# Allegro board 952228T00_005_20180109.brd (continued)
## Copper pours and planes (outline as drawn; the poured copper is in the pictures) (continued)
(no net) on BOTTOM: 84.28,6 83.04,6 83.04,5.19 82.96,5.12 81.31,5.12 81.16,5.27 81.16,6.64 80.53,7.27 77.05,7.27 76.72,6.94 76.72,5.32 76.89,5.14 79.08,5.14 80.02,4.2 83.32,4.2 83.65,4.53 84.26,4.53 84.31,4.58 84.31,5.98
FAN1_PWR on TOP: 24.77,9.31 24.77,7.12 24.39,6.74 22,6.74 21.93,6.82 21.93,10.27 28.23,16.57 37.84,16.57 38.05,16.36 38.05,14.49 29.95,14.49
FAN1_PWR on BOTTOM: 38.11,21.16 38.11,16.81 37.88,16.59 37.41,16.59 37.21,16.38 37.21,14.71 37.4,14.51 39.07,14.51 39.81,15.25 39.81,21.16
FAN1_PWR on BOTTOM: 24.42,6.72 22,6.72 21.83,6.89 21.83,9.2 22.13,9.51 24.52,9.51 24.67,9.36 24.67,6.97
FAN2_PWR on TOP: 79.59,7.48 82.33,7.48 82.34,7.49 88.04,7.49 90.53,9.98 90.53,17.13 90.56,17.16 90.56,18.15 90.28,18.43 90.28,18.68 90.06,18.9 88.6,18.9 88.59,18.89 88.59,11.01 87.05,9.47 79.64,9.47 79.59,9.43
FAN2_PWR on BOTTOM: 89.44,18.09 89.39,18.04 89.39,17.28 89.52,17.16 91.04,17.16 91.04,18.08 91.12,18.16 91.12,20.3 91.12,20.31 91.12,20.84 91.08,20.88 89.64,20.88 89.44,20.68
FAN2_PWR on BOTTOM: 82.3,7.58 79.71,7.58 79.43,7.86 79.43,8.6 79.79,8.95 82.3,8.95 82.35,8.9 82.35,7.63
FAN3_PWR on TOP: 131.66,7.99 102.22,7.99 102.22,9.59 130.97,9.59 131.2,9.81 131.2,13.17 134.32,16.29 143.01,16.29 143.7,15.61 143.7,14.67 135.77,14.67 133.18,12.08 133.18,9.51
FAN3_PWR on BOTTOM: 142.61,14.51 143.61,14.51 144.64,15.54 144.64,20.9 143.28,20.9 143.28,16.41 142.29,15.42 142.29,14.83
FAN3_PWR on BOTTOM: 102.24,8.77 103.64,8.77 103.74,8.67 103.74,6.64 103.61,6.51 102.37,6.51 102.22,6.66 102.22,8.75
FAN4_PWR on TOP: 194.98,20.1 185.94,11.07 185.94,10.87 187.28,9.53 187.78,9.53 197.11,18.86 197.11,19.75 196.76,20.1
FAN5_PWR on TOP: 247.76,15.66 247.94,15.83 247.94,18.72 248.17,18.95 249.47,18.95 249.82,18.61 249.82,15.15 248.57,13.9 218.7,13.9 217.99,14.62 204.12,14.62 202.57,13.07 200.97,13.07 200.9,13.14 200.9,14.49 202.62,16.22 227.32,16.22 227.88,15.66
FAN5_PWR on BOTTOM: 202.45,11.74 201.05,11.74 200.9,11.9 200.9,14.51 202.57,14.51 202.78,14.31 202.78,12.08
FAN_GND on TOP (solid shape): outline of 241 points within 9.48,20.07 16.48,27.08
FAN_GND on TOP (solid shape): outline of 241 points within 49.48,5.07 56.48,12.08
FAN_GND on TOP (solid shape): outline of 241 points within 149.48,5.07 156.48,12.08
FAN_GND on TOP (solid shape): outline of 241 points within 209.48,20.07 216.48,27.08
FAN_GND on TOP (solid shape): outline of 264 points within 112.85,18.45 121.11,26.7
FAN_GND on TOP (solid shape): outline of 264 points within 250.91,4.45 259.17,12.7
FAN_GND on BOTTOM (solid shape): outline of 241 points within 9.48,20.07 16.48,27.08
FAN_GND on BOTTOM (solid shape): outline of 241 points within 49.48,5.07 56.48,12.08
FAN_GND on BOTTOM (solid shape): outline of 241 points within 149.48,5.07 156.48,12.08
FAN_GND on BOTTOM (solid shape): outline of 241 points within 209.48,20.07 216.48,27.08
FAN_GND on BOTTOM (solid shape): outline of 264 points within 112.85,18.45 121.11,26.7
FAN_GND on BOTTOM (solid shape): outline of 264 points within 250.91,4.45 259.17,12.7
FAN_GND on TOP: outline of 155 points within 0.51,0.51 272.49,30.29 ; 10 cut-outs
FAN_GND on BOTTOM: outline of 145 points within 0.51,0.51 272.49,30.29 ; 25 cut-outs
FAN_GND on G02: outline of 86 points within 0.51,0.51 272.49,30.29
FAN_GND on T03: outline of 86 points within 0.51,0.51 272.49,30.29 ; 22 cut-outs
FAN_GND on P04: outline of 84 points within 0.51,0.51 272.49,30.29
FAN_GND on G05: outline of 84 points within 0.51,0.51 272.49,30.29
FAN_P3V3 on G05: 1.52,1.52 1.52,22.18 8.98,22.18 11.3,19.6 14.76,19.65 14.76,19.36 17.79,16.34 20.81,19.36 20.81,20.02 39.49,20.02 39.49,19.36 42.51,16.34 45.53,19.36 45.53,20.02 67.27,20.02 67.27,19.36 70.29,16.34 73.31,19.36 73.31,20.02 91.99,20.02 91.99,19.36 95.01,16.34 98.03,19.36 98.03,20.02 112.53,20.02 115.87,17.57 119.93,18.38 123.29,16.38 125.81,19.36 125.81,20.02 144.49,20.02 144.49,19.36 147.51,16.34 150.53,19.36 150.53,21.87 172.27,21.87 172.27,19.36 175.29,16.34 178.31,19.36 178.31,19.61 196.98,19.61 196.98,19.36 200.01,16.33 203.04,19.36 203.04,19.63 224.76,19.63 224.76,19.36 227.79,16.33 230.82,19.36 230.82,19.63 249.49,19.63 249.49,19.36 252.51,16.34 255.53,19.36 255.53,27.8 255.97,28.84 257.01,29.28 271.47,29.28 271.47,1.52 ; 3 cut-outs
FAN_P12V on BOTTOM (solid shape): 81.16,6.64 81.16,5.27 81.31,5.12 82.96,5.12 83.04,5.19 83.04,6 83.7,6 83.7,5.95 84.31,5.95 84.31,4.58 84.26,4.53 83.65,4.53 83.32,4.2 80.02,4.2 79.08,5.14 76.89,5.14 76.72,5.32 76.72,6.94 77.05,7.27 80.53,7.27
FAN_P12V on BOTTOM: 107.53,6.44 106.23,6.44 106.05,6.61 104.88,6.61 104.53,6.26 102.32,6.26 101.73,6.84 99.04,6.84 98.76,6.56 98.76,5.17 98.97,4.96 107.32,4.96 107.53,5.17
FAN_P12V on BOTTOM: 28.3,7.1 25.05,7.1 24.75,6.79 24.75,2.96 24.93,2.78 26.63,2.78 26.91,3.06 26.91,4.86 27.67,5.62 28.28,5.62 28.33,5.67 28.33,7.07
FAN_P12V on BOTTOM: 203.28,11.87 205.9,11.87 207.14,10.63 208.24,10.63 208.57,10.3 208.57,8.7 208.44,8.57 205.37,8.57 205.29,8.65 205.29,10.4 205.19,10.5 203.28,10.5 203.26,10.53 203.26,11.85
FAN_P12V on BOTTOM: 189.29,7.45 188.45,7.45 187.84,6.84 185.91,6.84 185.73,7.02 185.73,8.42 184.49,9.66 179.64,9.66 179.64,8.14 181.6,8.14 182.28,7.47 183.18,7.47 183.7,6.94 183.7,6.66 184.92,5.45 188.96,5.45 189.39,5.88 189.39,7.35
FAN_P12V on BOTTOM: 262.69,26.38 261.6,25.28 261.6,18.45 265.79,14.26 265.79,7.22 265.74,7.17 260.43,7.17 260.43,12.1 257.44,15.1 257.44,26.86 259.52,28.94 269.76,28.94 270.19,28.51 270.19,26.96 269.6,26.38
FAN_P12V on P04: 1.52,1.52 1.52,29.28 13.29,29.28 14.33,28.84 14.76,27.8 14.76,27.19 8.81,23.43 14.76,19.67 14.76,19.36 17.79,16.34 20.81,19.36 20.81,20.02 39.49,20.02 39.49,19.36 42.51,16.34 45.53,19.36 45.53,20.02 67.27,20.02 67.27,19.36 70.29,16.34 73.31,19.36 73.31,20.02 91.99,20.02 91.99,19.36 95.01,16.34 98.03,19.36 98.03,20.02 112.54,20.02 115.88,17.57 119.93,18.38 123.28,16.38 125.81,19.36 125.81,20.02 144.45,20.02 144.49,19.98 144.49,19.36 147.51,16.34 150.53,19.36 150.53,21.88 172.27,21.88 172.27,19.36 175.29,16.34 178.31,19.36 178.31,19.61 196.98,19.61 196.98,19.36 200.01,16.33 203.04,19.36 203.04,19.63 224.76,19.63 224.76,19.36 227.79,16.33 230.82,19.36 230.82,19.66 249.49,19.66 249.49,19.36 252.51,16.34 255.53,19.36 255.53,27.8 255.97,28.84 257.01,29.28 271.47,29.28 271.47,1.52 ; 3 cut-outs

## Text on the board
User.Comments: CR_3_2 | CR_3_3 | CR_3_5 | CR_3_4
Ref Des/Silkscreen Top: REV:00GP | PN:308.03045.005 | LABLE 25.4*9.5 | 95.2228T00
PAGE_OUTLINE: 2018.01.09 | UNLESS OTHERWISE SPECIFIED | DIMENSIONS ARE IN INCHES | TOLERANCES ON; | 2 PL DECIMALS +/- .010 | 3 PL DECIMALS +/- .005 | ANGLES +/- 5 | FRACTIONS + | ISSUED | CAD    Forward | ENGRG  Jenna | SIGNATURES | DATE | SCALE | SIZE | FSCM NO | DWG NO | SHEET | REV | DESCRIPTION | REVISIONS | APPROVED | D | 95.2228T00 | C | B | A | 7 | 6 | 5 | 4 | 3 | 2 | 1 | UfiSpace
BODY_CENTER: 14 | 13.BOARD MUST BE IDENTIFIED WITH APPROPRIATE VENDOR UL IDENTIFACTION MARK,DATE CODE. | 14.PCB MATERIAL UL FLAMMABILITY RATING(94V-0 MINIMUM) | 12.PCB VENDOR MUST BE UL QUALIFIED | 10.ALL COPPER FEATURES ON THE BOARD ARE TO BE FINISHED WITH OSP COAT. | 11.THIS IS A 6 LAYER BOARD. VENDER TO PROVIDE BOARD STACK-UP FOR IMPEDANCE | APPROVAL PRIOR TO BOARD FABRICATION.STACK-UP AND IMPEDANCE TO INCLUDE COPPER | PLANTING THICKNESS ON OUTER LAYERS. | OVER BARE COPPER PRIOR TO ANY PLATING FINISH PROCESSES | 2. ALL FINISHED BOARDS TO BE ELECTRICALLY TESTED. | 3. SILKSCREEN TO BE WHITE. NON-CONDUCTIVE , EPOXY INK OR EQUIVALENT. | 4. SOLDERMASK GREEN LIQUID PHOTO-IMAGABLE SMOBC SOLDERMASK TO BE APPLIED | 5. BOARD THICKNESS IS 0.0936"+/- 10% | 6 .NON-FUNCTIONAL PADS ON INTERNAL LAYERS MAY BE OMITTED. | 7 .TEARDROP TRACE ENTRY TO VIAS ON INTERNAL LAYERS, PROVIDED DRC RULES ARE MET. | 8 .ACCEPTABLE MINIMUM ANNULAR RING FOR VIA IS 0.001". | 9 .THIS IS A CONTROLLED IMPEDANCE BOARD. CONTROLS ARE AS FOLLOWS: | 1. MATERIAL:FR-4 OR EQUIVALENT. THE USE OF SINGLE PLY CONSTRUCION IS OPTIONAL | NOTES: (UNLESS OTHERWISE SPECIFIED) | IMPEDANCE SHALL BE 50 OHMS +/-10% ON OUTER 0.0009 INCH TRACES. | DETAIL  A | SCALE  1/1 | 0.51MM  0.18 | 30   3 | 2.36MM  0.23
User.6: 14.GOLD FINGER CONTACTS USE IPC 6012A REQUIREMENTS STATED IN TABLE 3-2.CLASS 2. | ELECTROLYTIC GOKD 30 MICROINCHES(0.00003).REFER DETAIL A FOR SIDE VIEW OF | THE THICKNESS FOR ELECTROLYTIC NICKEL IS 100 MICRQINCHES(0.0001)AND | GOLD FINGER.
User.11: 4pcs Fiducial(See Detail A) | 4xdia0.125+0.003-0.000 Tooling hole | 4xR0.200
User.12: TOP SIDE SOLDER PAST | 1     2
User.13: BOTTM SIDE SOLDER PAST | 2     2
User.14: TOP SIDE SILK SCREEN | 7     8
User.15: BOTTOM SIDE SILK SCREEN | 8      8
User.16: TOP SIDE SOLDERMASK | 5     8
User.17: BOTTOM SIDE SOLDERMASK | 6     8
User.18: : 1 TO 1 | FABRICATION
User.19: : 1 TO 2 | ASSY_TOP
User.20: : 2 TO 2 | ASSY_BOT | BOTTOM SIDE VIEW
User.22: +/-10 MILS | 0.0936 | CORE - 0.0315 1/1 | PRE-PREG - 0.0104 | PRE-PREG - 0.0054 | FOIL - 0.5 OZ. | NOTE: COPPER THICKNESS IS INCLUDED IN THE OVER ALL | BOARD THICKNESS SPECIFICATION | COMPONENT SIDE -LAYER1 | GND   PLANE    -LAYER2 | INNER 1 SIGNAL -LAYER3 | VCC   PLANE    -LAYER5 | SOLDER SIDE    -LAYER6 | INNER 2 SIGNAL -LAYER4
User.23: 1 | COMPONENT SIDE | 1     8
User.24: 2 | GND PLANE 1 | 2     8
User.25: 3 | POWER PLANE 2 | 3     8
User.26: 4 | POWER PLANE 1 | 4     8
User.27: 2018/01/09 | LAYER | PROJECT | P/N:308.03045.005 | VER:005 | H/W | CAD | SIGNATURES | Forward | Jenna | DATA | SHEET    OF | 95.2228T00 | GERBER | UfiSpace
User.28: TOP SIDE SOLDER PAST | & SILK | 1     2
User.29: & SILK | BOTTOM SIDE SOLDER PAST | 2     2
User.30: 2018/01/08 | SHEET | DWG NO | FSCM NO | SIZE | SCALE | DATE | SIGNATURES | ISSUED | CAD   Forward | ENGR  Jenna | UNLESS OTHERWISE SPECIFIED | DIMENSIONS ARE IN INCHES | TOLERANCES ON; | 2 PL DECIMALS +/- .010 | 3 PL DECIMALS +/- .005 | ANGLES +/- 5 | FRACTIONS + | APPROVED | REVISIONS | DESCRIPTION | REV | D | 95.2228T00 | B | C | A | 1 | 2 | 3 | 4 | 5 | 6 | 7 | UfiSapce
User.31: 2 OF 2 | PANEL DRAWING
User.32: GOLD PLATING FILM LAYER FOR BOTTOM | 1 | 2
User.33: 5 | GND PLANE 2 | 8
User.34: BOTTOM SIDE | 6 | 8
User.40: FIGURE | FHS | 8.0 | 10.0 | 20.0 | 44.0 | 45.0 | 118.0 | 138.0 | 181.0 | DRILL CHART: TOP to BOTTOM | ALL UNITS ARE IN MILS | TOLERANCE | +2.0/-5.0 | +2.0/-7.0 | +3.0/-3.0 | +2.0/-2.0 | +4.0/-4.0 | PLATED | NON-PLATED | QTY | 115 | 563 | 48 | 4 | 2 | 1
